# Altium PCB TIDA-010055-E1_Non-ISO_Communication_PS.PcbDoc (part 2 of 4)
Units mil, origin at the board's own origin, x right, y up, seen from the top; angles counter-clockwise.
Board outline 3937.01 x 3346.46 mil, 2 copper layers (Top Layer, Bottom Layer), stack 62 mil thick; 328 components, 142 nets, 761 pads, 214 vias.
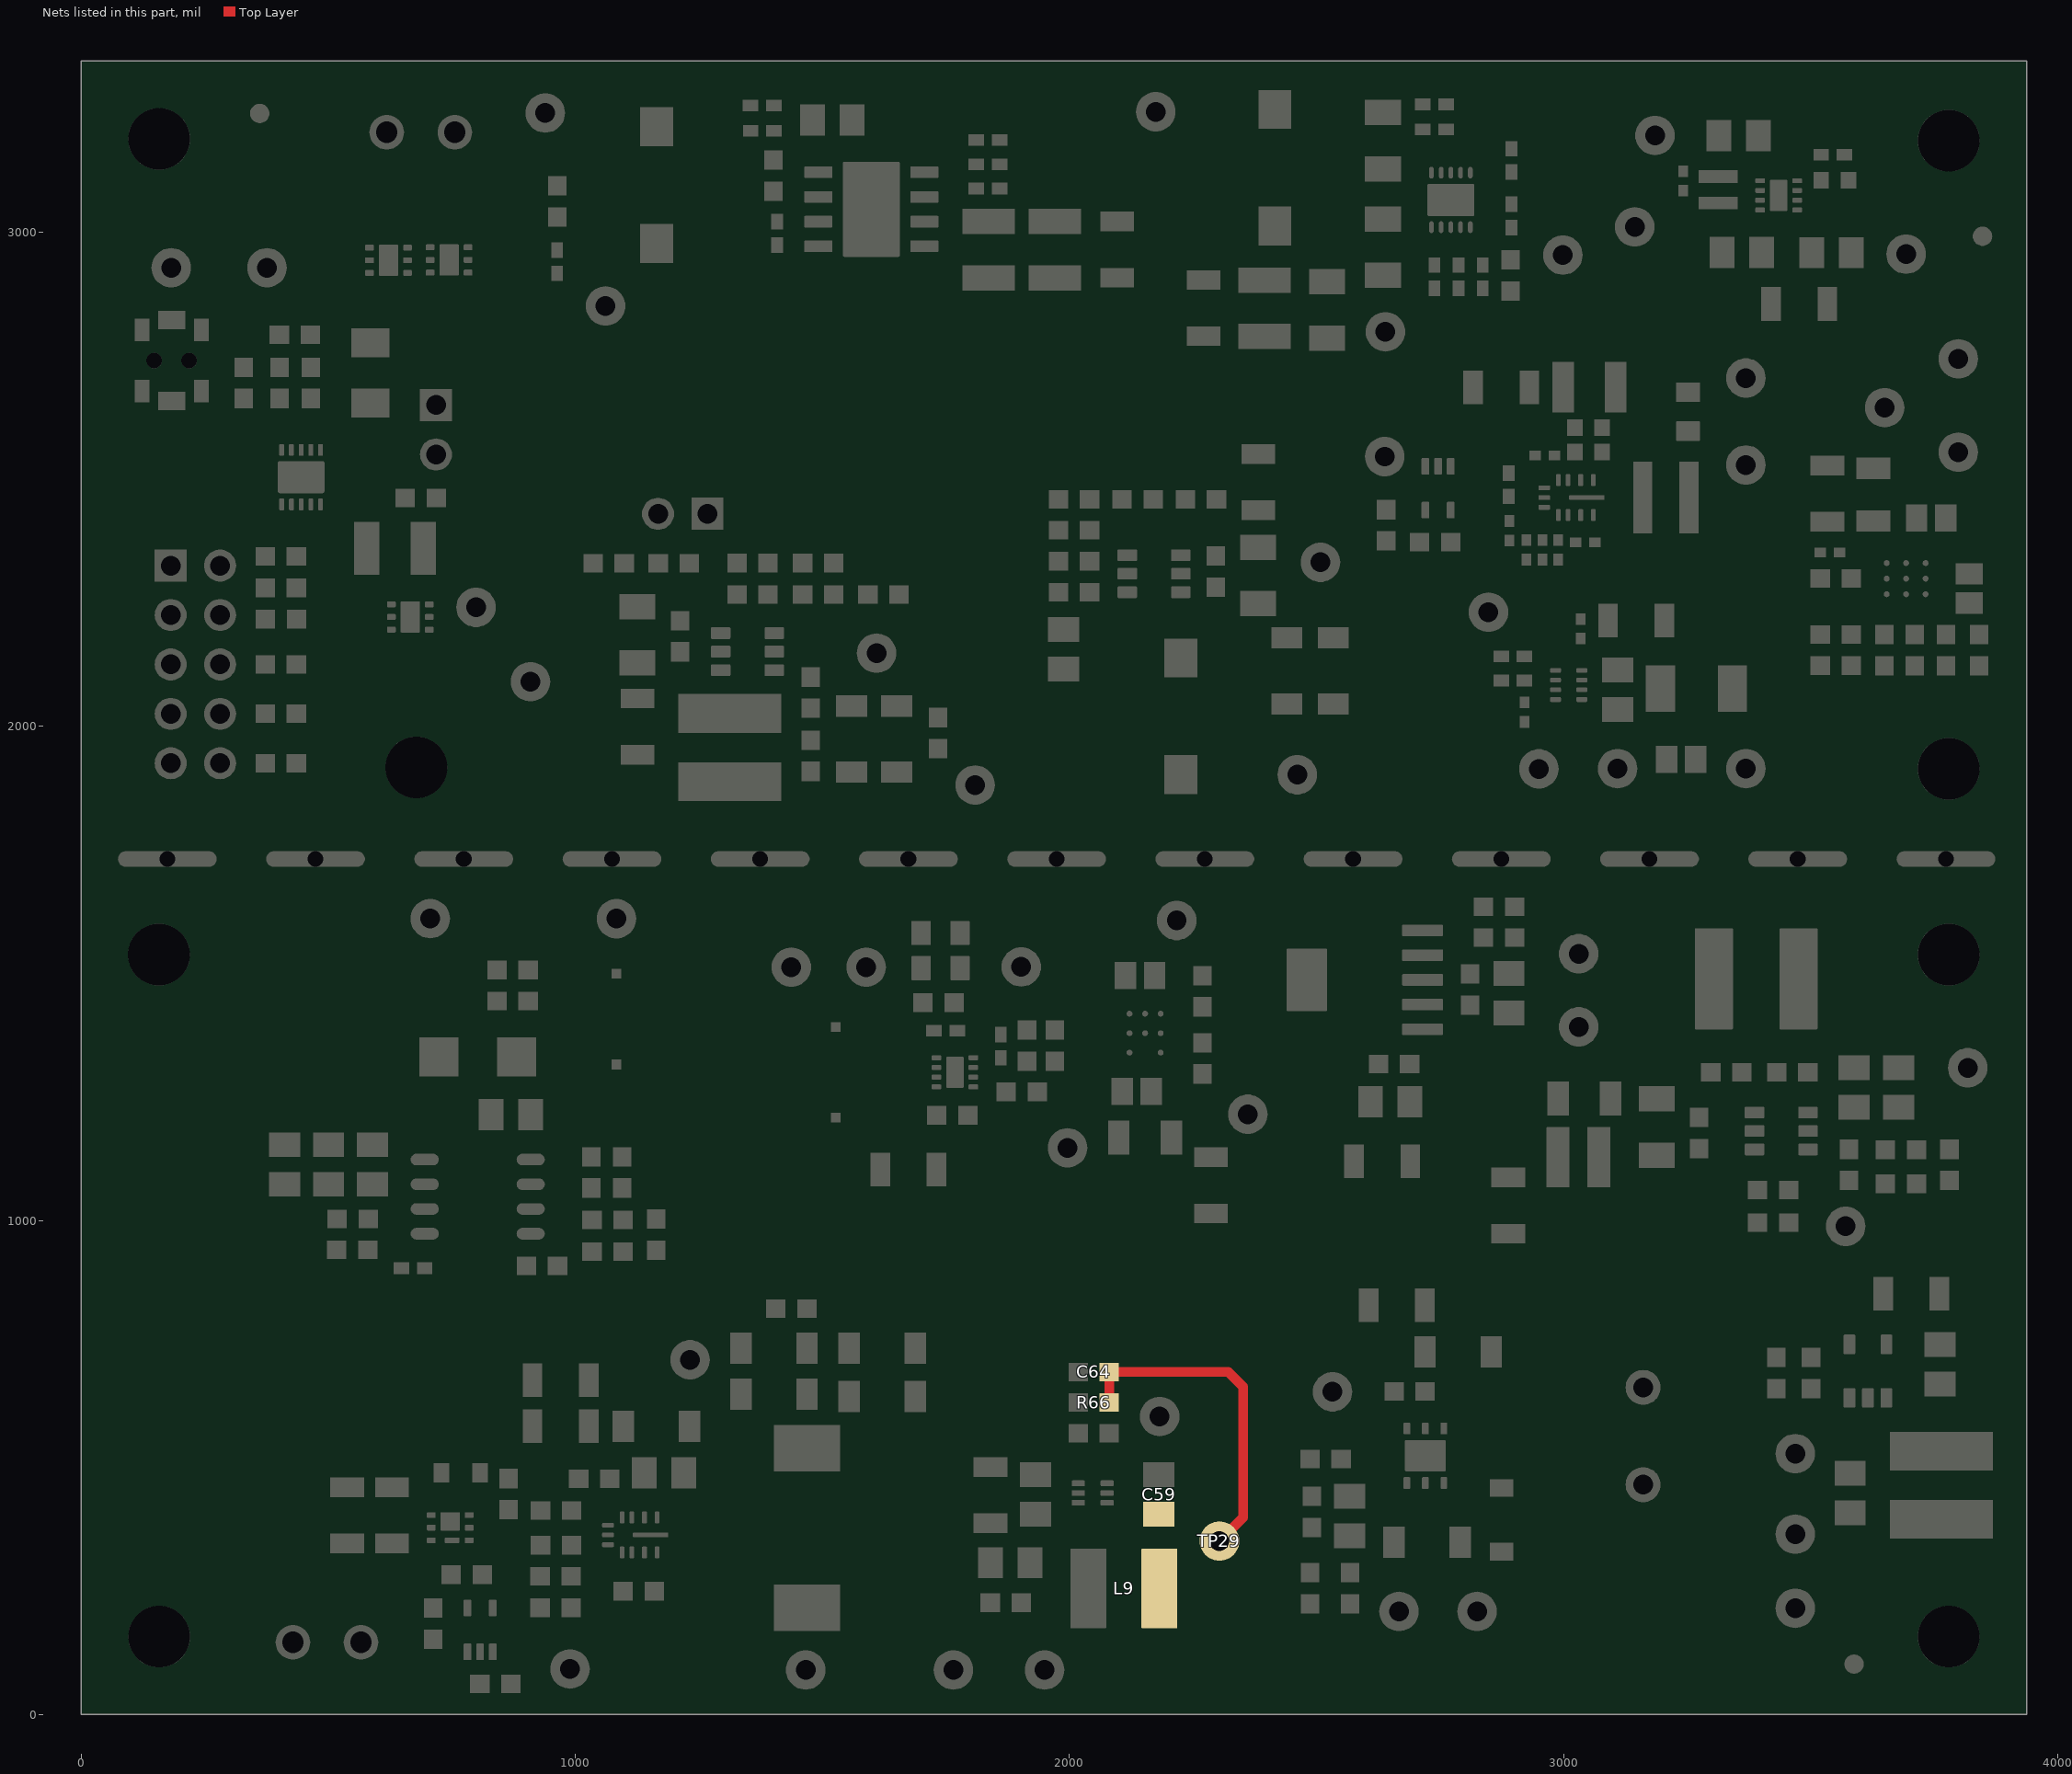
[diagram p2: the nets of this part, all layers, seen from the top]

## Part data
C1 C56: library part GRM155R61C103KA01D, "CAP, CERM, 0.01 µF, 16 V, +/- 10%, X5R, 0402", Cap_Case=0402, Manufacturer=KEMET, Supplier Part Number 1=399-11930-1-ND, TempCo=X5R, Tolerance_%=10, Value1=Unknown, Value2=16V, ValueDisplayed=0.01µF
C2: library part GRM188R61C105KA93D, "CAP, CERM, 1 µF, 16 V, +/- 10%, X5R, 0603", Cap_Case=0603, Manufacturer="Samsung Electro-Mechanics", Supplier Part Number 1=1276-1034-1-ND, TempCo=X5R, Tolerance_%=10, Value1=Unknown, Value2=16V, ValueDisplayed=1µF
C3: "CAP, CERM, 10 µF, 6.3 V, +/- 20%, X5R, 0603", Cap_Case=0603, Manufacturer=MuRata, Supplier Part Number 1=490-3896-1-ND, TempCo=X5R, Tolerance_%=20, Value1="0.009 ohm", Value2=6.3V, ValueDisplayed=10µF
C4: library part GRM1555C1H751JA01D, "CAP, CERM, 750 pF, 50 V, +/- 5%, C0G/NP0, 0402", Cap_Case=0402, Manufacturer=KEMET, Supplier Part Number 1=399-14469-1-ND, TempCo=C0G/NP0, Tolerance_%=5, Value1=Unknown, Value2=50V, ValueDisplayed=750pF
C5 C6 C14: library part GRM32ER72A225KA35L, "CAP, CERM, 2.2 µF, 100 V, +/- 10%, X7R, 1210", Cap_Case=1210, Manufacturer="TDK Corporation", Supplier Part Number 1=445-4497-1-ND, TempCo=X7R, Tolerance_%=10, Value1="0.007 ohm", Value2=100V, ValueDisplayed=2.2µF
C7 C50: library part GRM21BR71E104KA01L, "CAP, CERM, 0.1 µF, 25 V, +/- 10%, X7R, 0805", Cap_Case=0805, Manufacturer=KEMET, Supplier Part Number 1=399-1168-1-ND, TempCo=X7R, Tolerance_%=10, Value1=Unknown, Value2=25V, ValueDisplayed=0.1µF
C8: library part GRM188R71E104KA01D, "CAP, CERM, 0.1 µF, 25 V, +/- 10%, X7R, 0603", Cap_Case=0603, Manufacturer="Samsung Electro-Mechanics", Supplier Part Number 1=1276-1006-1-ND, TempCo=X7R, Tolerance_%=10, Value1=Unknown, Value2=25V, ValueDisplayed=0.1µF
C9: library part GRM31CR71E106KA12L, "CAP, CERM, 10 µF, 25 V, +/- 10%, X7R, 1206", Cap_Case=2220, Manufacturer="Samsung Electro-Mechanics", Supplier Part Number 1=1276-1804-1-ND, TempCo=X7R, Tolerance_%=10, Value1=Unknown, Value2=25V, ValueDisplayed=10µF
C10 C11: "CAP, CERM, 22 µF, 10 V, +/- 10%, X7R, AEC-Q200 Grade 1, 1206_190", Cap_Case=1206, Manufacturer=MuRata, Supplier Part Number 1=490-14439-2-ND, TempCo=X7R, Tolerance_%=10, Value1=Unknown, Value2=10V, ValueDisplayed=22µF
C12: library part CMP-0006751-4, "CAP, CERM, 100 pF, 25 V, +/- 10%, X7R, 0603", Cap_Case=0603, Manufacturer=AVX, Supplier Part Number 1=478-7899-6-ND, TempCo=X7R, Tolerance_%=10%, Value1=Unknown, Value2=25V, ValueDisplayed=100pF
C13 C17: library part GRM31CR72A105KA01L, "CAP, CERM, 1 µF, 100 V, +/- 10%, X7R, 1206", Cap_Case=2220, Manufacturer="TDK Corporation", Supplier Part Number 1=445-4467-1-ND, TempCo=X7R, Tolerance_%=10, Value1=Unknown, Value2=100V, ValueDisplayed=1µF
C15: library part GRM32ER71J106KA12L, "CAP, CERM, 10 µF, 63 V, +/- 10%, X7R, 1210", Cap_Case=1210, Manufacturer="Samsung Electro-Mechanics", Supplier Part Number 1=1276-3388-1-ND, TempCo=X7R, Tolerance_%=10, Value1=Unknown, Value2=63V, ValueDisplayed=10µF
C16: "CAP, CERM, 2.2 µF, 50 V, +/- 10%, X7R, 1206", Cap_Case=1206, Manufacturer="Taiyo Yuden", Supplier Part Number 1=587-2911-1-ND, TempCo=X7R, Tolerance_%=10, Value1=Unknown, Value2=50V, ValueDisplayed=2.2µF
C18: library part GRM188R71C223KA01D, "CAP, CERM, 0.022 µF, 16 V,+/- 10%, X7R, 0603", Cap_Case=0603, Manufacturer=KEMET, Supplier Part Number 1=399-1093-1-ND, TempCo=X7R, Tolerance_%=10, Value2=16V, ValueDisplayed=0.022µF
C19: library part GRM31CR71A226KE15L, "CAP, CERM, 22 µF, 10 V, +/- 10%, X7R, 1206", Cap_Case=1206, Manufacturer="Samsung Electro-Mechanics", Supplier Part Number 1=1276-2769-1-ND, TempCo=X7R, Tolerance_%=10, Value1=Unknown, Value2=10V, ValueDisplayed=22µF
C20: library part GRM155R71C473KA01D, "CAP, CERM, 0.047 µF, 16 V, +/- 10%, X7R, 0402", Cap_Case=0402, Manufacturer="Samsung Electro-Mechanics", Supplier Part Number 1=1276-1077-1-ND, TempCo=X7R, Tolerance_%=10, Value1=Unknown, Value2=16V, ValueDisplayed=0.047µF
C21: "CAP, CERM, 2.2 µF, 50 V,+/- 10%, X7R, 1206", Cap_Case=1206, Manufacturer="Taiyo Yuden", Supplier Part Number 1=587-2911-1-ND, TempCo=X7R, Tolerance_%=10, Value2=50V, ValueDisplayed=2.2µF
C22 C23 C27: library part GRM188R71H104KA93D, "CAP, CERM, 0.12µF ±10% 50V Ceramic Capacitor X7R 0603", Cap_Case=0603, Manufacturer=KEMET, Supplier Part Number 1=399-13273-1-ND, TempCo=X7R, Tolerance_%=10, Value2=50V, ValueDisplayed=0.1µF
C24 C29: "CAP, CERM, 22 pF, 50 V,+/- 5%, C0G/NP0, 0603", Cap_Case=0603, Manufacturer=AVX, Supplier Part Number 1=478-1167-1-ND, TempCo=C0G/NP0, Tolerance_%=5, Value1="0.259 ohm", Value2=50V, ValueDisplayed=22pF
C25 C26: library part GRM31CR71A226KE15L, "CAP, CERM, 22 µF, 10 V,+/- 10%, X7R, 1206", Cap_Case=1206, Manufacturer="Samsung Electro-Mechanics", Supplier Part Number 1=1276-3148-1-ND, TempCo=X7R, Tolerance_%=10, Value2=10V, ValueDisplayed=22µF
C28: library part UMK107AB7105KA-T, "CAP, CERM,  1UF 50V X5R 0603", Cap_Case=0603, Manufacturer="Taiyo Yuden", Supplier Part Number 1=587-2400-1-ND, TempCo=X7R, Tolerance_%=10, Value2=50V, ValueDisplayed=1µF
C30: library part CGA6M3X7S2A475K200AB, "CAP, CERM, 4.7 µF, 100 V, +/- 10%, X7S, AEC-Q200 Grade 1, 1210", Cap_Case=1210_220, Manufacturer=TDK, Supplier Part Number 1=445-7005-1-ND, TempCo=X7S, Tolerance_%=10, Value1="0.004236 ohm", Value2=100V, ValueDisplayed=4.7µF
C31 C32: library part CGA3E3X7S2A473K080AB, "CAP, CERM, 0.047 µF, 100 V,+/- 10%, X7S, AEC-Q200 Grade 1, 0603", Cap_Case=0603, Manufacturer=TDK, Supplier Part Number 1=445-6936-1-ND, TempCo=X7S, Tolerance_%=10, Value1="0.089796 ohm", Value2=100V, ValueDisplayed=0.047µF
C33: library part CMP-0006659-2, "CAP, CERM, 0.1 uF, 25 V, +/- 10%, X7R, 0402", Cap_Case=0402, Manufacturer=MuRata, PartNumber=GRM155R71E104KE14D, Supplier Part Number 1=490-10698-1-ND, TempCo=X7R, Tolerance_%=10%, Value1=Unknown, Value2=25V, ValueDisplayed=0.1uF
C34: library part GRM1555C1E200JA01D, "CAP, CERM, 20 pF, 25 V,+/- 5%, C0G/NP0, 0402", Cap_Case=0402, Manufacturer=MuRata, Supplier Part Number 1=490-11364-1-ND, TempCo=C0G/NP0, Tolerance_%=5, Value2=25V, ValueDisplayed=20pF
C35: "CAP, CERM, 4.7 µF, 10 V,+/- 20%, X7R, 0805", Cap_Case=0805, Manufacturer=TDK, Supplier Part Number 1=445-1605-1-ND, TempCo=X7R, Tolerance_%=20, Value2=10V, ValueDisplayed=4.7µF
C36 C44 C45: library part GRM21BR60J226ME39L, "CAP, CERM, 22 µF, 6.3 V, +/- 20%, X5R, 0805", Cap_Case=0805, Manufacturer="Samsung Electro-Mechanics", Supplier Part Number 1=1276-6687-1-ND, TempCo=X5R, Tolerance_%=20, Value1="0.009 ohm", Value2=6.3V, ValueDisplayed=22µF
C37: library part CMP-0006300-2, "CAP, CERM, 1 uF, 10 V, +/- 10%, X7S, 0402", Cap_Case=0402, Manufacturer="Murata Electronics North America", PartNumber=GCM155C71A105KE38D, Supplier Part Number 1=490-13409-1-ND, TempCo=X7S, Tolerance_%=10%, Value1="0.011416 ohm", Value2=10V, ValueDisplayed=1uF
C38 C86 C87 C89: library part CMP-0008316-2, "CAP, CERM, 10 uF, 10 V, +/- 20%, X7R, 0805", Cap_Case=0805, Manufacturer="TDK Corporation", PartNumber=C2012X7R1A106M125AC, Supplier Part Number 1=445-7592-1-ND, TempCo=X7R, Tolerance_%=20%, Value1=Unknown, Value2=10V, ValueDisplayed=10uF
C39: library part CMP-0006416-2, "CAP, CERM, 120 pF, 50 V, +/- 1%, C0G/NP0, 0402", Cap_Case=0402, Manufacturer="Samsung Electro-Mechanics", PartNumber=CL05C121JB5NNNC, Supplier Part Number 1=1276-1640-1-ND, TempCo=C0G/NP0, Tolerance_%=1%, Value1=Unknown, Value2=50V, ValueDisplayed=120pF
C40: library part GRM188R60J106ME84, "CAP, CERM, 10 µF, 6.3 V, +/- 20%, X5R, 0603", Cap_Case=0603, Manufacturer="Samsung Electro-Mechanics", Supplier Part Number 1=1276-1119-1-ND, TempCo=X5R, Tolerance_%=20, Value1=Unknown, Value2=6.3V, ValueDisplayed=10µF
C41: library part GRM1555C1H220FA01D, "CAP, CERM, 22 pF, 50 V, +/- 1%, C0G/NP0, 0402", Cap_Case=0402, Manufacturer="Samsung Electro-Mechanics", Supplier Part Number 1=1276-6849-1-ND, TempCo=C0G/NP0, Tolerance_%=1, Value1=Unknown, Value2=50V, ValueDisplayed=22pF
C42: "CAP, CERM, 470 pF, 50 V, +/- 10%, X7R, AEC-Q200 Grade 1, 0402", Cap_Case=0402, Manufacturer=MuRata, Supplier Part Number 1=490-4913-1-ND, TempCo=X7R, Tolerance_%=10, Value1=Unknown, Value2=50V, ValueDisplayed=470pF
C43: "CAP, CERM, 2.2 µF, 16 V,+/- 20%, X5R, 0603", Cap_Case=0603, Manufacturer="Wurth Elektronik", Supplier Part Number 1=732-7915-1-ND, TempCo=X5R, Tolerance_%=20, Value2=16V, ValueDisplayed=2.2µF
C46 C47: library part 06035A101JAT2A, "CAP, CERM, 100 pF, 50 V, +/- 5%, C0G/NP0, 0603", Cap_Case=0603, Manufacturer=AVX, Supplier Part Number 1=478-6022-1-ND, TempCo=C0G/NP0, Tolerance_%=5, Value1="0.119 ohm", Value2=50V, ValueDisplayed=100pF
C48 C49: library part GRM21BR61E106KA73L, "CAP, CERM, 10 µF, 25 V, +/- 10%, X5R, 0805", Cap_Case=0805, Manufacturer="TDK Corporation", Supplier Part Number 1=445-14387-1-ND, TempCo=X5R, Tolerance_%=10, Value1=Unknown, Value2=25V, ValueDisplayed=10µF
C51 C52: "CAP, CERM, 47 µF, 6.3 V,+/- 20%, X5R, 0603", Cap_Case=0603, Manufacturer=MuRata, Supplier Part Number 1=490-13247-1-ND, TempCo=X5R, Tolerance_%=20, Value2=6.3V, ValueDisplayed=47µF
C53 C54: library part GRM21BR71E475KA73L, "CAP, CERM, 4.7 µF, 25 V,+/- 10%, X7R, 0805", Cap_Case=0805, Manufacturer="TDK Corporation", Supplier Part Number 1=445-5972-1-ND, TempCo=X7R, Tolerance_%=10, Value2=25V, ValueDisplayed=4.7µF
C55: "CAP, CERM, 0.01 µF, 50 V,+/- 5%, X7R, 0805", Cap_Case=0805, Manufacturer=AVX, Supplier Part Number 1=478-3768-1-ND, TempCo=X7R, Tolerance_%=5, Value1="0.078 ohm", Value2=50V, ValueDisplayed=0.01µF
C57: "CAP, CERM, 1000 pF, 50 V,+/- 10%, C0G/NP0, 0603", Cap_Case=0603, Manufacturer=AVX, Supplier Part Number 1=478-3718-1-ND, TempCo=C0G/NP0, Tolerance_%=10, Value1="0.048 ohm", Value2=50V, ValueDisplayed=1000pF
C58: library part GRM1885C1H470FA01J, "CAP, CERM, 47 pF, 50 V,+/- 1%, C0G/NP0, 0603", Cap_Case=0603, Manufacturer="AVX Corporation", Supplier Part Number 1=478-6203-1-ND, TempCo=C0G/NP0, Tolerance_%=1, Value2=50V, ValueDisplayed=47pF
C59: library part CMP-0008315-2, "CAP, CERM, 10 uF, 10 V, +/- 10%, X7R, 0805", Cap_Case=0805, Manufacturer="Samsung Electro-Mechanics", PartNumber=CL21B106KPQNFNE, Supplier Part Number 1=1276-2934-1-ND, TempCo=X7R, Tolerance_%=10%, Value1="0.003 ohm", Value2=10V, ValueDisplayed=10uF
C60: "CAP, CERM, 4.7 µF, 35 V, +/- 10%, X7R, 0805", Cap_Case=0805, Manufacturer=TDK, Supplier Part Number 1=445-7555-1-ND, TempCo=X7R, Tolerance_%=10, Value1="0.002346 ohm", Value2=35V, ValueDisplayed=4.7µF
C61: library part CMP-0008802-2, "CAP, CERM, 10 uF, 50 V, +/- 10%, X7R, 1206", Cap_Case=1206, Manufacturer=Samsung, Supplier Part Number 1=1276-6767-1-ND, TempCo=X7R, Tolerance_%=10%, Value1=Unknown, Value2=50V, ValueDisplayed=10uF
C62: library part CMP-0009026-2, "CAP, CERM, 4.7 uF, 50 V, +/- 10%, X7R, 1206_190", Cap_Case=1206, Manufacturer="Taiyo Yuden", Supplier Part Number 1=587-2994-2-ND, TempCo=X7R, Tolerance_%=10%, Value1=Unknown, Value2=50V, ValueDisplayed=4.7uF
C63: library part CMP-0007449-4, "CAP, CERM, 330 pF, 50 V, +/- 10%, X7R, 0603", Cap_Case=0603, Manufacturer="Samsung Electro-Mechanics", PartNumber=CL10B331KB8NNNC, Supplier Part Number 1=1276-1787-1-ND, TempCo=X7R, Tolerance_%=10%, Value1=Unknown, Value2=50V, ValueDisplayed=330pF
C64: "CAP, CERM, 6.8 pF, 50 V,+/- 4%, C0G/NP0, 0603", Cap_Case=0603, Manufacturer=AVX, Supplier Part Number 1=478-1161-1-ND, TempCo=C0G/NP0, Tolerance_%=4, Value1="0.505 ohm", Value2=50V, ValueDisplayed=6.8pF
C65: library part C1608X7R1H104K080AA, "CAP, CERM, 0.1 µF, 50 V, +/- 10%, X7R, 0603", Cap_Case=0603, Manufacturer="Samsung Electro-Mechanics", Supplier Part Number 1=1276-1000-1-ND, TempCo=X7R, Tolerance_%=10, Value1="0.0296 ohm", Value2=50V, ValueDisplayed=0.1µF
C66: library part CMP-0008705-2, "CAP, CERM, 10 uF, 35 V, +/- 10%, X7R, 1206", Cap_Case=1206_180, Manufacturer=TDK, Supplier Part Number 1=445-14799-1-ND, TempCo=X7R, Tolerance_%=10%, Value1="0.002229 ohm", Value2=35V, ValueDisplayed=10uF
C67: library part CMP-0008422-2, "CAP, CERM, 0.22 uF, 50 V, +/- 10%, X7R, 0805", Cap_Case=0805, Manufacturer="Taiyo Yuden", Supplier Part Number 1=587-1287-1-ND, TempCo=X7R, Tolerance_%=10%, Value1=Unknown, Value2=50V, ValueDisplayed=0.22uF
C68 C69 C70 C71: library part CMP-0008805-2, "CAP, CERM, 22 uF, 16 V, +/- 20%, X7R, 1206_190", Cap_Case=1206, Manufacturer="Taiyo Yuden", Supplier Part Number 1=587-4319-1-ND, TempCo=X7R, Tolerance_%=20%, Value1=Unknown, Value2=16V, ValueDisplayed=22uF
C72: library part CMP-0007119-4, "CAP, CERM, 0.1 uF, 16 V, +/- 10%, X7R, 0603", Cap_Case=0603, Manufacturer="Taiyo Yuden", Supplier Part Number 1=587-1240-1-ND, TempCo=X7R, Tolerance_%=10%, Value1=Unknown, Value2=16V, ValueDisplayed=0.1uF
C73: "CAP, CERM, 1 µF, 16 V,+/- 10%, X7R, 0603", Cap_Case=0603, Manufacturer="Wurth Elektronik", Supplier Part Number 1=732-7971-1-ND, TempCo=X7R, Tolerance_%=10, Value1=Unknown, Value2=16V, ValueDisplayed=1µF
C74: library part 06033C104JAT2A, "0.1µF ±10% 35V Ceramic Capacitor X5R 0603", Cap_Case=0603, Manufacturer="Taiyo Yuden", Supplier Part Number 1=587-3357-1-ND, TempCo=X7R, Tolerance_%=5, Value1="0.05 ohm", Value2=25V, ValueDisplayed=0.1µF
C75: library part C0603C104K5RACTU, "CAP, CERM, 0.1µF ±10% 50V Ceramic Capacitor X7R 0603", Cap_Case=0603, Manufacturer=Kemet, Supplier Part Number 1=399-14105-1-ND, TempCo=X7R, Tolerance_%=10, Value2=50V, ValueDisplayed=0.1µF
C76: "CAP, CERM, 4.7 µF, 25 V, +/- 10%, X5R, 0805", Cap_Case=0805, Manufacturer=TDK, Supplier Part Number 1=445-4116-1-ND, TempCo=X5R, Tolerance_%=10, Value1=Unknown, Value2=25V, ValueDisplayed=4.7µF
C77: library part C2012X5R0J226M, "CAP, CERM, 22 µF, 6.3 V, +/- 20%, X5R, 0805", Cap_Case=0805, Manufacturer="Samsung Electro-Mechanics", Supplier Part Number 1=1276-6687-1-ND, TempCo=X5R, Tolerance_%=20, Value1="0.0018 ohm", Value2=6.3V, ValueDisplayed=22µF
C78: library part GRM188R70J104KA01D, "CAP, CERM, 0.1 µF, 6.3 V, +/- 10%, X7R, 0603", Cap_Case=0603, Manufacturer=KEMET, Supplier Part Number 1=399-15351-1-ND, TempCo=X7R, Tolerance_%=10, Value1=Unknown, Value2=6.3V, ValueDisplayed=0.1µF
C79: "CAP, CERM, 0.1 µF, 25 V, +/- 10%, X7R, 0603", Cap_Case=0603, Manufacturer="Wurth Elektronik", Supplier Part Number 1=710-885012206071, TempCo=X7R, Tolerance_%=10, Value1=Unknown, Value2=25V, ValueDisplayed=0.1µF
C80: "CAP, CERM, 10 µF, 35 V, +/- 10%, X7R, 1206", Cap_Case=1206, Manufacturer="Taiyo Yuden", Supplier Part Number 1=587-3007-1-ND, TempCo=X7R, Tolerance_%=10, Value1=Unknown, Value2=35V, ValueDisplayed=10µF
C81 C85 C88: library part C3216X5R1E476M160AC, "CAP, CERM, 47 µF, 25 V,+/- 20%, X5R, 1206", Cap_Case=1206, Manufacturer="Samsung Electro-Mechanics", Supplier Part Number 1=1276-3063-1-ND, TempCo=X5R, Tolerance_%=20, Value2=25V, ValueDisplayed=47µF
C82 C83: library part GRM21BZ71A226ME15L, "CAP, CERM, 22 µF, 10 V, +/- 20%, X7R, 0805", Cap_Case=0805, Manufacturer="Samsung Electro-Mechanics", Supplier Part Number 1=1276-1822-1-ND, TempCo=X7R, Tolerance_%=20, Value1=Unknown, Value2=10V, ValueDisplayed=22µF
C84: library part GRM1885C1H220JA01D, "CAP, CERM, 22 pF, 50 V, +/- 5%, C0G/NP0, 0603", Cap_Case=0603, Manufacturer="Samsung Electro-Mechanics", Supplier Part Number 1=1276-1023-1-ND, TempCo=C0G/NP0, Tolerance_%=5, Value1=Unknown, Value2=50V, ValueDisplayed=22pF
C90: library part CMP-0008316-2, "CAP, CERM, 10 uF, 10 V, +/- 20%, X7R, 0805", Cap_Case=0805, Manufacturer="TDK Corporation", PartNumber=C2012X7R1A106M125AC, TempCo=X7R, Tolerance_%=20%, Value1=Unknown, Value2=10V, ValueDisplayed=10uF
C91 C92 C93: "CAP, CERM, 22 µF, 6.3 V,+/- 10%, X5R, 0805", Cap_Case=0805, Manufacturer="Taiyo Yuden", Supplier Part Number 1=587-1468-1-ND, TempCo=X5R, Tolerance_%=10, Value1="0.002 ohm", Value2=6.3V, ValueDisplayed=22µF
D1: library part CMP-0028353-1, "Diode, Schottky, 40 V, 3 A, SMA", Manufacturer="Diodes Inc.", Supplier Part Number 1=B340A-FDICT-ND, Value1=3A, Value2=0.5V
D2: library part CMP-0028547-1, "Diode, Schottky, 30 V, 1 A, SOD-123", Manufacturer="ON Semiconductor", Supplier Part Number 1=MBR130T1GOSCT-ND, Value1=1A, Value2=0.47V
D3: "LED, Green, SMD", Color=Green, Manufacturer=OSRAM, Supplier Part Number 1=475-1406-1-ND, Value1=W, Value2=1.8V
FID1 FID2 FID3: "Fiducial mark.  There is nothing to buy or mount.", Manufacturer=N/A
H1 H2 H3 H4 H9 H10 H11 H12: library part "PMSSS 440 0025 PH", "MACHINE SCREW PAN PHILLIPS 4-40", Manufacturer="Essentra Components", Supplier Part Number 1=RPC1579-ND
H5 H6 H7 H8 H13 H14 H15 H16: "Standoff, Hex, 1\"L #4-40 Nylon", Manufacturer=Keystone, Supplier Part Number 1=36-1902E-ND
J1 J4: "Header, 100mil, 2x1, Gold, TH", Color=Black, Current_A=3, Manufacturer="Sullins Connector Solutions", Supplier Part Number 1=S1011E-02-ND, Voltage_V=1800
J2 J5: "Conn Term Block, 2POS, 3.5mm, TH", Manufacturer="Phoenix Contact", Supplier Part Number 1=277-5719-ND
J3: "Header, 100mil, 5x2, Tin, TH", Color=Black, Current_A=3, Manufacturer="Sullins Connector Solutions", Supplier Part Number 1=S2012E-05-ND, Voltage_V=1800
L1: "Inductor, Shielded Drum Core, Metal Composite, 330uH, 0.39A, 1.15 ohm, SMD", Manufacturer="Wurth Elektronik eiSos", Supplier Part Number 1=732-1201-1-ND, Value1="1.15 ohm", Value2=0.39A, ValueDisplayed=330µH
L2: "Inductor, Shielded Drum Core, Ferrite, 22uH, 1.41A, 0.09 ohm, SMD", Manufacturer="Wurth Elektronik eiSos", Supplier Part Number 1=732-1194-1-ND, Value1="0.09 ohm", Value2=1.41A, ValueDisplayed=22µH
L3: "Inductor, Shielded Drum Core, Metal Composite, 180uH, 0.51A, 0.68 ohm, SMD", Manufacturer="Wurth Elektronik eiSos", Supplier Part Number 1=732-1201-1-ND, Value1="0.68 ohm", Value2=0.51A, ValueDisplayed=180µH
L4: library part CMP-0064461-2, "Inductor, Shielded Drum Core, Ferrite, 15 uH, 1.4 A, 0.118 ohm, SMD", Manufacturer="Wurth Elektronik", Supplier Part Number 1=732-3038-1-ND, Value1="0.118 ohm", Value2=1.4A, ValueDisplayed=15uH
L5: library part CMP-0081728-1, "Inductor, Shielded, Metal Composite, 10 µH, 2.7 A, 0.11 ohm, SMD", Manufacturer="Wurth Elektronik", Supplier Part Number 1=732-11206-1-ND, Value1="0.11 ohm", Value2=2.7A, ValueDisplayed=10µH
L6: "Inductor, Shielded Drum Core, Powdered Iron, 1.5uH, 3.8A, 0.0348 ohm, SMD", Manufacturer="Wurth Elektronik eiSos", Supplier Part Number 1=732-3346-1-ND, Value1="0.0348 ohm", Value2=3.8A, ValueDisplayed=1.5µH
L7: "Inductor, Shielded Drum Core, Ferrite, 1uH, 2.6A, 0.028 ohm, SMD", Manufacturer="Wurth Elektronik eiSos", Supplier Part Number 1=732-1016-1-ND, Value1="0.028 ohm", Value2=2.6A, ValueDisplayed=1µH
L8: "Inductor, Shielded Drum Core, Ferrite, 6.8uH, 1.2A, 0.095 ohm, SMD", Manufacturer="Wurth Elektronik eiSos", Supplier Part Number 1=732-1023-1-ND, Value1="0.095 ohm", Value2=1.2A, ValueDisplayed=6.8µH
L9: library part CMP-0058727-1, "Inductor, Wirewound, Ferrite, 2.2 uH, 2.6 A, 0.036 ohm, SMD", Manufacturer=MuRata, Supplier Part Number 1=490-7778-1-ND, Value1="0.036 ohm", Value2=2.6A, ValueDisplayed=2.2uH
L10: library part CMP-0064520-2, "Inductor, Shielded Drum Core, Metal Composite, 22 uH, 3 A, 0.038 ohm, TH", Manufacturer="Wurth Elektronik", Supplier Part Number 1=732-3414-ND, Value1="0.038 ohm", Value2=3A, ValueDisplayed=22uH
L11: library part CMP-0064666-2, "Inductor, Shielded, Metal Composite, 11 uH, 5.3 A, 0.014 ohm, SMD", Manufacturer="Wurth Elektronik", Supplier Part Number 1=732-2414-1-ND, Value1="0.014 ohm", Value2=5.3A, ValueDisplayed=11uH
L12: "Inductor, Shielded Drum Core, Ferrite, 22 µH, 1.1 A, 0.185 ohm, SMD", Manufacturer="Wurth Elektronik", Supplier Part Number 1=732-3034-1-ND, Value1="0.185 ohm", Value2=1.1A, ValueDisplayed=22µH
L13: "Inductor, 4.7 µH, 1.12 A, 0.12 ohm, SMD", Manufacturer=Coilank, Value1="0.12 ohm", Value2=1.12A, ValueDisplayed=4.7µH
L14: "Inductor, 3.3 µH, 3.91 A, 0.026 ohm, SMD", Manufacturer=Coilank, Value1="0.026 ohm", Value2=3.91A, ValueDisplayed=3.3µH
L15: "Inductor, Shielded Drum Core, Ferrite, 470 nH, 2 A, 0.059 ohm, SMD", Manufacturer=TDK, Supplier Part Number 1=445-6606-1-ND, Value1="0.059 ohm", Value2=2A, ValueDisplayed=470nH
LBL1: library part THT-14-423-10, "Thermal Transfer Printable Labels, 0.650\" W x 0.200\" H - 10,000 per roll", Alternate Manufacturer=-, Manufacturer=Brady, Supplier Part Number 1=2065596
Logo1: library part CMP-0074769-1
Logo2: library part Pb-Free
Logo3: library part FCC_disclaimer, "FCC_disclaimer"
Logo4: library part ESD_Susceptible, "ESD Susceptible Symbol"
Q1: "MOSFET, N-CH, 30 V, 22 A, DQK0006C (WSON-6)", Alternate Manufacturer=None, Manufacturer="Texas Instruments", Supplier Part Number 1=296-37193-1-ND, Value1="0.029 ohm", Value2="2.4 nC"
R1: "RES, 88.7 k, 1%, 0.063 W, 0402", Manufacturer=Vishay-Dale, Power_W=0.063, Supplier Part Number 1=541-88.7KLCT-ND, TempCo="100 ppm/C", Tolerance_%=1, Value1=1%, Value2=0.063W, Value_Code=88k7, ValueDisplayed=88.7k
R2: "RES, 51.1 k, 1%, 0.063 W, 0402", Manufacturer=Vishay-Dale, Power_W=0.063, Supplier Part Number 1=541-51.1KLCT-ND, TempCo="100 ppm/C", Tolerance_%=1, Value1=1%, Value2=0.063W, Value_Code=51k1, ValueDisplayed=51.1k
R3: "RES, 10.0 k, 1%, 0.063 W, 0402", Manufacturer=Vishay-Dale, Power_W=0.063, Supplier Part Number 1=541-10.0KLCT-ND, TempCo="100 ppm/C", Tolerance_%=1, Value1=1%, Value2=0.063W, Value_Code=10k0, ValueDisplayed=10.0k
R4: "RES, 13.0 k, 1%, 0.063 W, 0402", Manufacturer=Vishay-Dale, Power_W=0.063, Supplier Part Number 1=541-13.0KLCT-ND, TempCo="100 ppm/C", Tolerance_%=1, Value1=1%, Value2=0.063W, Value_Code=13k0, ValueDisplayed=13.0k
R5: "RES, 2.15, 1%, 0.063 W, 0402", Manufacturer=Vishay-Dale, Power_W=0.063, Supplier Part Number 1=541-2.15LLCT-ND, TempCo="100 ppm/C", Tolerance_%=1, Value1=1%, Value2=0.063W, Value_Code=2R15, ValueDisplayed=2.15
R6: "RES, 6.19 k, 1%, 0.125 W, 0805", Manufacturer=Vishay-Dale, Power_W=0.125, Supplier Part Number 1=541-6.19KCCT-ND, TempCo="100 ppm/C", Tolerance_%=1, Value1=1%, Value2=0.125W, Value_Code=6k19, ValueDisplayed=6.19k
R7 R14 R40 R45 R87 R94 R95 R97 R98 R99 R100 R101 R102 R103: "RES, 0, 5%, 0.1 W, 0603", Manufacturer=Vishay-Dale, Power_W=0.1, Supplier Part Number 1=541-0.0GCT-ND, TempCo="200 ppm/C", Tolerance_%=5, Value1=5%, Value2=0.1W, Value_Code=0000, ValueDisplayed=0
R8: "RES, 510 k, 5%, 0.1 W, 0603", Manufacturer=Vishay-Dale, Power_W=0.1, Supplier Part Number 1=541-510KGCT-ND, TempCo="200 ppm/C", Tolerance_%=5, Value1=5%, Value2=0.1W, Value_Code=510k
R9 R91: "RES, 49.9 k, 1%, 0.1 W, 0603", Manufacturer=Vishay-Dale, Power_W=0.1, Supplier Part Number 1=541-49.9KHCT-ND, TempCo="100 ppm/C", Tolerance_%=1, Value1=1%, Value2=0.1W, Value_Code=49k9, ValueDisplayed=49.9k
R10: library part CMP-0021990-4, "RES, 100 k, 1%, 0.1 W, AEC-Q200 Grade 0, 0603", Manufacturer=Vishay-Dale, Power_W=100mW, Supplier Part Number 1=541-100KHCT-ND, TempCo="100 ppm/C", Tolerance_%=1%, Value2=0.1W, Value_Code=100k
R11: "RES, 118 k, 1%, 0.1 W, 0603", Manufacturer=Vishay-Dale, Power_W=0.1, Supplier Part Number 1=541-118KHCT-ND, TempCo="100 ppm/C", Tolerance_%=1, Value1=1%, Value2=0.1W, Value_Code=118k
R12 R21: "RES, 13.3 k, 1%, 0.1 W, 0603", Manufacturer=Vishay-Dale, Power_W=0.1, Supplier Part Number 1=541-13.3KHCT-ND, TempCo="100 ppm/C", Tolerance_%=1, Value1=1%, Value2=0.1W, Value_Code=13k3, ValueDisplayed=13.3k
R13: "RES, 887 k, 1%, 0.1 W, 0603", Manufacturer=Vishay-Dale, Power_W=0.1, Supplier Part Number 1=541-887KHCT-ND, TempCo="100 ppm/C", Tolerance_%=1, Value1=1%, Value2=0.1W, Value_Code=887k
R15: "RES, 29.4 k, 1%, 0.1 W, 0603", Manufacturer=Vishay-Dale, Power_W=0.1, Supplier Part Number 1=541-29.4KHCT-ND, TempCo="100 ppm/C", Tolerance_%=1, Value1=1%, Value2=0.1W, Value_Code=29k4, ValueDisplayed=29.4k
R16: "RES, 2.00 M, 1%, 0.063 W, 0402", Manufacturer=Vishay-Dale, Power_W=0.063, Supplier Part Number 1=541-2.00MLCT-ND, TempCo="100 ppm/C", Tolerance_%=1, Value1=1%, Value2=0.063W, Value_Code=2M00, ValueDisplayed=2.00M
R17: "RES, 499 k, 1%, 0.063 W, 0402", Manufacturer=Vishay-Dale, Power_W=0.063, Supplier Part Number 1=541-499KLCT-ND, TempCo="100 ppm/C", Tolerance_%=1, Value1=1%, Value2=0.063W, Value_Code=499k
R18: "RES, 34.0 k, 1%, 0.1 W, 0603", Manufacturer=Vishay-Dale, Power_W=0.1, Supplier Part Number 1=541-34.0KHCT-ND, TempCo="100 ppm/C", Tolerance_%=1, Value1=1%, Value2=0.1W, Value_Code=34k0, ValueDisplayed=34.0k
R19: "RES, 357 k, 1%, 0.063 W, 0402", Manufacturer=Vishay-Dale, Power_W=0.063, Supplier Part Number 1=541-357KLCT-ND, TempCo="100 ppm/C", Tolerance_%=1, Value1=1%, Value2=0.063W, Value_Code=357k
R20: "RES, 7.50 k, 1%, 0.1 W, 0603", Manufacturer=Vishay-Dale, Power_W=0.1, Supplier Part Number 1=541-7.50KHCT-ND, TempCo="100 ppm/C", Tolerance_%=1, Value1=1%, Value2=0.1W, Value_Code=7k50, ValueDisplayed=7.50k
R22: "RES, 26.7 k, 1%, 0.1 W, 0603", Manufacturer=Vishay-Dale, Power_W=0.1, Supplier Part Number 1=541-26.7KHCT-ND, TempCo="100 ppm/C", Tolerance_%=1, Value1=1%, Value2=0.1W, Value_Code=26k7, ValueDisplayed=26.7k
R23: "RES, 44.2 k, 1%, 0.1 W, 0603", Manufacturer=Vishay-Dale, Power_W=0.1, Supplier Part Number 1=541-44.2KHCT-ND, TempCo="100 ppm/C", Tolerance_%=1, Value1=1%, Value2=0.1W, Value_Code=44k2, ValueDisplayed=44.2k
R24: "RES, 267 k, 1%, 0.1 W, 0603", Manufacturer=Vishay-Dale, Power_W=0.1, Supplier Part Number 1=541-267KHCT-ND, TempCo="100 ppm/C", Tolerance_%=1, Value1=1%, Value2=0.1W, Value_Code=267k
R25 R33 R35: "RES, 100 k, 1%, 0.063 W, 0402", Manufacturer=Vishay-Dale, Power_W=0.063, Supplier Part Number 1=541-100KLCT-ND, TempCo="100 ppm/C", Tolerance_%=1, Value1=1%, Value2=0.063W, Value_Code=100k
R26: "RES, 294 k, 1%, 0.063 W, 0402", Manufacturer=Vishay-Dale, Power_W=0.063, Supplier Part Number 1=541-294KLCT-ND, TempCo="100 ppm/C", Tolerance_%=1, Value1=1%, Value2=0.063W, Value_Code=294k
R27: "RES, 34.0 k, 1%, 0.063 W, 0402", Manufacturer=Vishay-Dale, Power_W=0.063, Supplier Part Number 1=541-34.0KLCT-ND, TempCo="100 ppm/C", Tolerance_%=1, Value1=1%, Value2=0.063W, Value_Code=34k0, ValueDisplayed=34.0k
R28: "RES, 402 k, 1%, 0.1 W, 0603", Manufacturer=Vishay-Dale, Power_W=0.1, Supplier Part Number 1=541-402KHCT-ND, TempCo="100 ppm/C", Tolerance_%=1, Value1=1%, Value2=0.1W, Value_Code=402k
R29: "RES, 49.9, 1%, 0.1 W, 0603", Manufacturer=Vishay-Dale, Power_W=0.1, Supplier Part Number 1=541-49.9HCT-ND, TempCo="100 ppm/C", Tolerance_%=1, Value1=1%, Value2=0.1W, Value_Code=49R9, ValueDisplayed=49.9
R30: "RES, 133 k, 1%, 0.1 W, 0603", Manufacturer=Vishay-Dale, Power_W=0.1, Supplier Part Number 1=541-133KHCT-ND, TempCo="100 ppm/C", Tolerance_%=1, Value1=1%, Value2=0.1W, Value_Code=133k
R31: "RES, 102 k, 1%, 0.1 W, 0603", Manufacturer=Vishay-Dale, Power_W=0.1, Supplier Part Number 1=541-102KHCT-ND, TempCo="100 ppm/C", Tolerance_%=1, Value1=1%, Value2=0.1W, Value_Code=102k
R32: "RES, 25.5 k, 1%, 0.1 W, 0603", Manufacturer=Vishay-Dale, Power_W=0.1, Supplier Part Number 1=541-25.5KHCT-ND, TempCo="100 ppm/C", Tolerance_%=1, Value1=1%, Value2=0.1W, Value_Code=25k5, ValueDisplayed=25.5k
R34: library part CRCW0402100KFKED, "RES, 100 k, 1%, 0.063 W, 0402", Manufacturer=Vishay-Dale, Power_W=0.063, Supplier Part Number 1=541-100KLCT-ND, TempCo="100 ppm/C", Tolerance_%=1, Value1=1%, Value2=0.063W, Value_Code=100k
R36 R104: library part CMP-0025958-2, "RES, 10.0 k, 1%, 0.063 W, 0402", Manufacturer=Vishay-Dale, PartNumber=CRCW040210K0FKED, Power_W=63mW, Supplier Part Number 1=541-10.0KLCT-ND, TempCo="100 ppm/C", Tolerance_%=1%, Value2=0.063W, Value_Code=10k0, ValueDisplayed=10.0k
R37: library part CMP-0026196-1, "RES, 24.9 k, 1%, 0.063 W, 0402", Manufacturer=Vishay-Dale, Power_W=63mW, Supplier Part Number 1=541-24.9KLCT-ND, TempCo="100 ppm/C", Tolerance_%=1%, Value2=0.063W, Value_Code=24k9, ValueDisplayed=24.9k
R38: library part CMP-0026669-1, "RES, 150 k, 1%, 0.1 W, AEC-Q200 Grade 0, 0402", Manufacturer=Panasonic, Power_W=100mW, Supplier Part Number 1=P150KLCT-ND, TempCo="100 ppm/C", Tolerance_%=1%, Value2=0.1W, Value_Code=150k
R39: library part CMP-0025950-2, "RES, 100 k, 1%, 0.063 W, 0402", Manufacturer=Vishay-Dale, PartNumber=CRCW0402100KFKED, Power_W=63mW, Supplier Part Number 1=541-100KLCT-ND, TempCo="100 ppm/C", Tolerance_%=1%, Value2=0.063W, Value_Code=100k
R41: "RES, 64.9 k, 1%, 0.1 W, 0603", Manufacturer="Yageo America", Power_W=0.1, Supplier Part Number 1=311-64.9KHRCT-ND, TempCo="200 ppm/C", Tolerance_%=1, Value1=1%, Value2=0.1W, Value_Code=64k9, ValueDisplayed=64.9k
R42: "RES, 38.3 k, 1%, 0.1 W, 0603", Manufacturer="Yageo America", Power_W=0.1, Supplier Part Number 1=311-38.3KHRCT-ND, TempCo="200 ppm/C", Tolerance_%=1, Value1=1%, Value2=0.1W, Value_Code=38k3, ValueDisplayed=38.3k
R43: "RES, 4.22 k, 1%, 0.1 W, 0603", Manufacturer=Vishay-Dale, Power_W=0.1, Supplier Part Number 1=541-4.22KHCT-ND, TempCo="100 ppm/C", Tolerance_%=1, Value1=1%, Value2=0.1W, Value_Code=4k22, ValueDisplayed=4.22k
R44: "RES, 4.02 k, 1%, 0.1 W, 0603", Manufacturer=Vishay-Dale, Power_W=0.1, Supplier Part Number 1=541-4.02KHCT-ND, TempCo="100 ppm/C", Tolerance_%=1, Value1=1%, Value2=0.1W, Value_Code=4k02, ValueDisplayed=4.02k
R46: "RES, 332 k, 1%, 0.1 W, 0603", Manufacturer=Vishay-Dale, Power_W=0.1, Supplier Part Number 1=541-332KHCT-ND, TempCo="100 ppm/C", Tolerance_%=1, Value1=1%, Value2=0.1W, Value_Code=332k
R47: "RES, 10.2 k, 1%, 0.1 W, 0603", Manufacturer=Vishay-Dale, Power_W=0.1, Supplier Part Number 1=541-10.2KHCT-ND, TempCo="100 ppm/C", Tolerance_%=1, Value1=1%, Value2=0.1W, Value_Code=10k2, ValueDisplayed=10.2k
R48: "RES, 68.1 k, 1%, 0.1 W, 0603", Manufacturer="Yageo America", Power_W=0.1, Supplier Part Number 1=311-68.1KHRCT-ND, TempCo="200 ppm/C", Tolerance_%=1, Value1=1%, Value2=0.1W, Value_Code=68k1, ValueDisplayed=68.1k
R49: "RES, 3.24 k, 1%, 0.1 W, 0603", Manufacturer=Vishay-Dale, Power_W=0.1, Supplier Part Number 1=541-3.24KHCT-ND, TempCo="100 ppm/C", Tolerance_%=1, Value1=1%, Value2=0.1W, Value_Code=3k24, ValueDisplayed=3.24k
R50: "RES, 29.4 k, 1%, 0.1 W, 0603", Manufacturer="Yageo America", Power_W=0.1, Supplier Part Number 1=311-29.4KHRCT-ND, TempCo="200 ppm/C", Tolerance_%=1, Value1=1%, Value2=0.1W, Value_Code=29k4, ValueDisplayed=29.4k
R51 R52 R53 R54 R55 R56 R57 R58 R59 R60 R61 R63 R68 R82 R85 R86 R93 R96 R105: "RES, 0, 1%, 0.5 W, 1206", Manufacturer=Keystone, Power_W=0.5, Supplier Part Number 1=36-5108CT-ND, TempCo=ppm/C, Tolerance_%=1, Value1=1%, Value2=0.5W, Value_Code=0
R62: "RES, 0, 5%, 0.1 W, 0603", Manufacturer=Panasonic, Power_W=0.1, Supplier Part Number 1=P0.0GCT-ND, TempCo="600 ppm/C", Tolerance_%=5, Value1=5%, Value2=0.1W, Value_Code=0000, ValueDisplayed=0
R64 R67 R69 R75 R76: library part CMP-0023363-3, "RES, 100 k, 0.1%, 0.1 W, AEC-Q200 Grade 0, 0603", Manufacturer=Panasonic, Power_W=100mW, Supplier Part Number 1=P100KDBCT-ND, TempCo="25 ppm/C", Tolerance_%=0.1%, Value2=0.1W, Value_Code=100k
R65: library part CMP-0019302-2, "RES, 475 k, 0.5%, 0.1 W, 0805", Manufacturer="Susumu Co Ltd", Power_W=100mW, Supplier Part Number 1=RR12P475KDCT-ND, TempCo="25 ppm/C", Tolerance_%=0.5%, Value2=0.1W, Value_Code=475k
R66: "RES, 453 k, 1%, 0.1 W, 0603", Manufacturer="Yageo America", Power_W=0.1, Supplier Part Number 1=311-453KHRCT-ND, TempCo="200 ppm/C", Tolerance_%=1, Value1=1%, Value2=0.1W, Value_Code=453k
R70: library part CMP-0019636-2, "RES, 182 k, 0.1%, 0.125 W, 0805", Manufacturer="Yageo America", Power_W=125mW, Supplier Part Number 1=YAG1798CT-ND, TempCo="25 ppm/C", Tolerance_%=0.1%, Value2=0.125W, Value_Code=182k
R71 R72 R74: library part CMP-0023343-3, "RES, 0, 1%, 0.1 W, AEC-Q200 Grade 0, 0603", Manufacturer="Stackpole Electronics Inc", Power_W=100mW, Supplier Part Number 1=RMCF0603ZT0R00CT-ND, TempCo=ppm/C, Tolerance_%=1%, Value2=0.1W, Value_Code=0
R73: library part CMP-0023404-3, "RES, 10.0 k, 0.1%, 0.1 W, 0603", Manufacturer="Susumu Co Ltd", Power_W=100mW, Supplier Part Number 1=RG16P10.0KBCT-ND, TempCo="25 ppm/C", Tolerance_%=0.1%, Value2=0.1W, Value_Code=10k0, ValueDisplayed=10.0k
R77: library part CMP-0023990-3, "RES, 24.9 k, 0.1%, 0.1 W, 0603", Manufacturer="Yageo America", Power_W=100mW, Supplier Part Number 1=YAG1599CT-ND, TempCo="25 ppm/C", Tolerance_%=0.1%, Value2=0.1W, Value_Code=24k9, ValueDisplayed=24.9k
R78 R80: "RES, 300, 5%, 0.1 W, 0603", Manufacturer=Vishay-Dale, Power_W=0.1, Supplier Part Number 1=541-300GCT-ND, TempCo="200 ppm/C", Tolerance_%=5, Value1=5%, Value2=0.1W, Value_Code=300R, ValueDisplayed=300
R79: "RES, 0, 1%, 0.1 W, AEC-Q200 Grade 0, 0603", Manufacturer="Stackpole Electronics Inc", Power_W=0.1, Supplier Part Number 1=RMCF0603ZT0R00CT-ND, TempCo=ppm/C, Tolerance_%=1, Value1=1%, Value2=0.1W, Value_Code=0
R81: "RES, 47.0 k, 0.1%, 0.1 W, 0603", Manufacturer="Susumu Co Ltd", Power_W=0.1, Supplier Part Number 1=RG16P47.0KBCT-ND, TempCo="25 ppm/C", Value1=0.1%, Value2=0.1W, Value_Code=47k0, ValueDisplayed=47.0k
R83: "RES, 61.9 k, 1%, 0.1 W, 0603", Manufacturer=Vishay-Dale, Power_W=0.1, Supplier Part Number 1=541-61.9KHCT-ND, TempCo="100 ppm/C", Tolerance_%=1, Value1=1%, Value2=0.1W, Value_Code=61k9, ValueDisplayed=61.9k
R84: "RES, 20.0 k, 1%, 0.1 W, 0603", Manufacturer=Vishay-Dale, Power_W=0.1, Supplier Part Number 1=541-20.0KHCT-ND, TempCo="100 ppm/C", Tolerance_%=1, Value1=1%, Value2=0.1W, Value_Code=20k0, ValueDisplayed=20.0k
R88: "RES, 80.6 k, 1%, 0.1 W, 0603", Manufacturer=Vishay-Dale, Power_W=0.1, Supplier Part Number 1=541-80.6KHCT-ND, TempCo="100 ppm/C", Tolerance_%=1, Value1=1%, Value2=0.1W, Value_Code=80k6, ValueDisplayed=80.6k
R89: "RES, 33.2 k, 1%, 0.1 W, 0603", Manufacturer=Vishay-Dale, Power_W=0.1, Supplier Part Number 1=541-33.2KHCT-ND, TempCo="100 ppm/C", Tolerance_%=1, Value1=1%, Value2=0.1W, Value_Code=33k2, ValueDisplayed=33.2k
R90: "RES, 51, 5%, 0.1 W, 0603", Manufacturer=Vishay-Dale, Power_W=0.1, Supplier Part Number 1=541-51GCT-ND, TempCo="200 ppm/C", Tolerance_%=5, Value1=5%, Value2=0.1W, Value_Code=51R0, ValueDisplayed=51
R92: "RES, 10.0 k, 1%, 0.1 W, 0603", Manufacturer="Vishay Draloric", Power_W=0.1, Supplier Part Number 1=541-1784-1-ND, TempCo="100 ppm/C", Tolerance_%=1, Value1=1%, Value2=0.1W, Value_Code=10k0, ValueDisplayed=10.0k
R106: "RES, 487 k, 1%, 0.063 W, 0402", Manufacturer=Vishay-Dale, Power_W=0.063, Supplier Part Number 1=541-487KLCT-ND, TempCo="100 ppm/C", Tolerance_%=1, Value1=1%, Value2=0.063W, Value_Code=487k
R107: "RES, 1.00 M, 1%, 0.063 W, 0402", Manufacturer="Yageo America", Power_W=0.063, Supplier Part Number 1=311-1.00MLRCT-ND, TempCo="100 ppm/C", Tolerance_%=1, Value1=1%, Value2=0.063W, Value_Code=1M00, ValueDisplayed=1.00M
R108: "RES, 162 k, 1%, 0.1 W, 0603", Manufacturer="Yageo America", Power_W=0.1, Supplier Part Number 1=311-162KHRCT-ND, TempCo="200 ppm/C", Tolerance_%=1, Value1=1%, Value2=0.1W, Value_Code=162k
S1: "Switch, SPST-NO,  Off-Mom, 0.05A, 12VDC, SMD", CurrentRating_mA=50, Manufacturer="C&K Components", Supplier Part Number 1=CKN10505CT-ND
TP1 TP3 TP7 TP9 TP10 TP13 TP15 TP20 TP22 TP24 TP29 TP33 TP43 TP44 TP46 TP48 TP49 TP51: "Test Point, Miniature, Red, TH", Color=Red, Manufacturer=Keystone, Supplier Part Number 1=36-5000-ND
TP2 TP5 TP8 TP11 TP12 TP16 TP18 TP21 TP23 TP25 TP31 TP34 TP39 TP45 TP47 TP50: "Test Point, Miniature, Black, TH", Color=Black, Manufacturer=Keystone, Supplier Part Number 1=36-5001-ND
TP4 TP6 TP14 TP17 TP19 TP27 TP28 TP30 TP32 TP35 TP36 TP38 TP40 TP42: "Test Point, Miniature, White, TH", Color=White, Manufacturer=Keystone, Supplier Part Number 1=36-5002-ND
TP26 TP41: "Test Point, Miniature, Red, TH", Manufacturer=Keystone, Supplier Part Number 1=5000K-ND
TP37: library part CMP-0055138-1, "Test Point, Miniature, Black, TH", Color=Black, Manufacturer=Keystone, Supplier Part Number 1=36-5001-ND
U1: "100V, 600mA Constant On-Time Synchronous Buck Regulator, DDA0008B", Alternate Manufacturer="Texas Instruments", Alternate PartNumber=LM5017MR/NOPB, Supplier Part Number 1=296-41308-1-ND
U2: "4.5-V TO 28-V INPUT, 2-A OUTPUT, EMI FRIENDLY SYNCHRONUOUS STEP-DOWN CONVERTOR, DDC0006A", Alternate Manufacturer="Texas Instruments", Alternate PartNumber=TPS54202DDCT, Supplier Part Number 1=296-46470-1-ND
U3 U7: library part CMP-0013424-7, "33-V Precision Surge Protection Clamp, DRV0006A (WSON-6)", Alternate Manufacturer="Texas Instruments", Alternate PartNumber=TVS3300DRVT, Supplier Part Number 1=296-47565-1-ND
U4: "7V - 57V, 800mA Industrial eFuse with Integrated Reverse Polarity Protection, DRC0010J (VSON-10)", Alternate Manufacturer="Texas Instruments", Alternate PartNumber=TPS26625DRCR
U5: library part CMP-0077833-1, "27-V Precision Surge Protection Clamp, DRV0006A (WSON-6)", Alternate Manufacturer="Texas Instruments", Supplier Part Number 1=TVS2700DRVR-ND
U6: "3.0-V to 65-V Input, 150-mA Output, Ultra-Low Quiescent (ULQ) Synchronous Step-Down Voltage Regulator, DRC0010J", Alternate Manufacturer="Texas Instruments", Alternate PartNumber=LM5165DRCT, Supplier Part Number 1=296-46273-2-ND
U8: library part CMP-0065098-3, "4V to 36 V 0.6 A Synchronous Step-Down Converter, DBV0006A (SOT-23-6)", Alternate Manufacturer="Texas Instruments", Alternate PartNumber=TPS560430XFDBVT, Supplier Part Number 1=TPS560430XFDBVT-ND
U9: library part CMP-0077274-3, "65-V 0.6-A Synchronous Step-Down Converter, RNX0012B (VQFN-HR-12)", Alternate Manufacturer="Texas Instruments", Alternate PartNumber=LMR36006BRNXT
U10: library part CMP-0065148-2, "2.5-V to 5.5-V, 1-, 2-, 3-A Step-Down Converter with DCS-Control, DLC0008A (SON-HR-8)", Alternate Manufacturer="Texas Instruments", Supplier Part Number 1=296-48383-2-ND
U11: "1.2A High Efficient Step Down Converter in 2x2mm SON Package, DSG0008A (WSON-8)", Alternate Manufacturer="Texas Instruments", Alternate PartNumber=TLV62080DSGT, Supplier Part Number 1=296-39270-1-ND
U12: library part CMP-0036669-1, "Single Output Fast Transient Response LDO, 1 A, Adjustable 1.2 to 20 V Output, 2.2 to 20 V Input, 6-pin SOT-223 (DCQ), -40 to 125 degC, Green (RoHS & no Sb/Br)", Manufacturer="Texas Instruments", Supplier Part Number 1=296-39489-1-ND
U13: library part CMP-0037667-1, "Buck Step Down Regulator with 3.5 to 28 V Input and 0.8 to 25 V Output, -40 to 150 degC, 8-Pin SOIC (D), Green (RoHS & no Sb/Br)", Manufacturer="Texas Instruments", Rating=Catalog, Supplier Part Number 1=296-23626-5-ND, Switch Current Limit(Typ)(A)=3.5
U14: library part CMP-0013407-3, "2-A High Efficiency Step-Down Converter in SOT Package, DRL0006A (SOT-6)", Alternate Manufacturer="Texas Instruments", Supplier Part Number 1=296-47563-1-ND
U15: library part CMP-0072695-3, "520kHz/1.6MHz - Space-Efficient Boost and SEPIC DC-DC Regulator, 6-pin LLP, Pb-Free", Manufacturer="Texas Instruments", PackageTopMarking=ZXYTT*2735X, PowerWise=N, Supplier Part Number 1=LM2735XSD/NOPBCT-ND
U16: library part CMP-0065235-5, "3.8-V to 36-V 2-A Synchronous Step-Down Voltage Regulator, RNX0012B (VQFN-HR-12)", Alternate Manufacturer="Texas Instruments", Alternate PartNumber=LMR33630ARNXT, Supplier Part Number 1=296-49764-1-ND
U17: "SINGLE SCHMITT-TRIGGER BUFFER, DCK0005A (SOT-SC70-5)", Alternate Manufacturer="Texas Instruments", Alternate PartNumber=SN74LVC1G17DCKT, Supplier Part Number 1=296-11934-1-ND
U18: library part CMP-0051390-2, "Single Buffer/Driver With Open-Drain Output, DCK0005A, LARGE T&R", F @ Nom Voltage(Max)(Mhz)=150, Generic Part Number=SN74LVC1G07, ICC @ Nom Voltage(Max)(mA)=0.01, Manufacturer="Texas Instruments", Operating Temperature Range(C)="-40 to 125,-40 to 85", Rating=Catalog, Supplier Part Number 1=296-8486-1-ND, tpd @ Nom Voltage(Max)(ns)=8.6,6,4.7,4, Voltage(Nom)(V)=1.8,2.5,3.3,5
U19: library part TPS560200DBV, "4.5V to 18V Input, 500mA Synchronous Step Down SWIFT Converter with Advanced Eco-mode, DBV0005A", Alternate Manufacturer="Texas Instruments"
U20: "4.5-V to 17-V Input, 2-A Synchronous Step-Down Voltage Regulator, DDC0006A (SOT-23-T-6)", Alternate Manufacturer="Texas Instruments", Alternate PartNumber=TPS561201DDCT
U21: library part CMP-0081865-1, "600mA Fully Integrated, Low Noise Step-Down Converter Module in MicroSiP(TM) Package, SIP0008A (uSIP-8)", Alternate Manufacturer="Texas Instruments", Alternate PartNumber=TPS826721SIPT, Operating Temperature Range="-40 to 85 C", Rating=Catalog
U22: library part CMP-0067293-1, "200-mA Step Down Converter MicroSiP Module with 360nA quiescent current, SIP0009F (uSIP-9)", Alternate Manufacturer="Texas Instruments", Alternate PartNumber=TPS82740ASIPT
U23: library part CMP-0067001-2, "2A High Efficient Step Down Converter in 2x2mm SON Package, TLV62084, DSG0008A (WSON-8)", Alternate Manufacturer="Texas Instruments", Alternate PartNumber=TLV62084DSGT
ZZ1: library part AssemblyNoteLabel, Alternate Manufacturer=-
ZZ2 ZZ3 ZZ4: library part AssemblyNote, Alternate Manufacturer=-

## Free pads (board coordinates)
  oval 200x32 hole 32 slot 200 at 0 deg unplated mask+10: 0(174,1731.42) 0(474,1731.42) 0(774,1731.42) 0(1074,1731.42) 0(1374,1731.42) 0(1674,1731.42) 0(1974,1731.42) 0(2274,1731.42) 0(2574,1731.42) 0(2874,1731.42) 0(3174,1731.42) 0(3474,1731.42) 0(3774,1731.42)

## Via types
v1: diameter 24, hole 12, Top Layer to Bottom Layer, 179 vias
v2: diameter 19.68, hole 7.87, Top Layer to Bottom Layer, 28 vias
v3: diameter 19.68, hole 7.87, Top Layer to Bottom Layer, tented both sides, 4 vias
v4: diameter 16, hole 8, Top Layer to Bottom Layer, 2 vias
v5: diameter 32, hole 16, Top Layer to Bottom Layer, 1 vias

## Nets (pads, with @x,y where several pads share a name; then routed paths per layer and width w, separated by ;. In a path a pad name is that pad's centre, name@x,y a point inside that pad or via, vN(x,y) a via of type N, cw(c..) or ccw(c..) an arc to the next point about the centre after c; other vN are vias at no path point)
3.3V/2A: C59.1 C64.1 L9.2 R66.2 TP29.1 | length 677.4
  Top Layer w20: R66.2@2080.5,631.19 C64.1@2080.5,693.19 2321.31,693.19 2351.54,662.96 2351.54,398.96 TP29.1@2303.54,350.96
